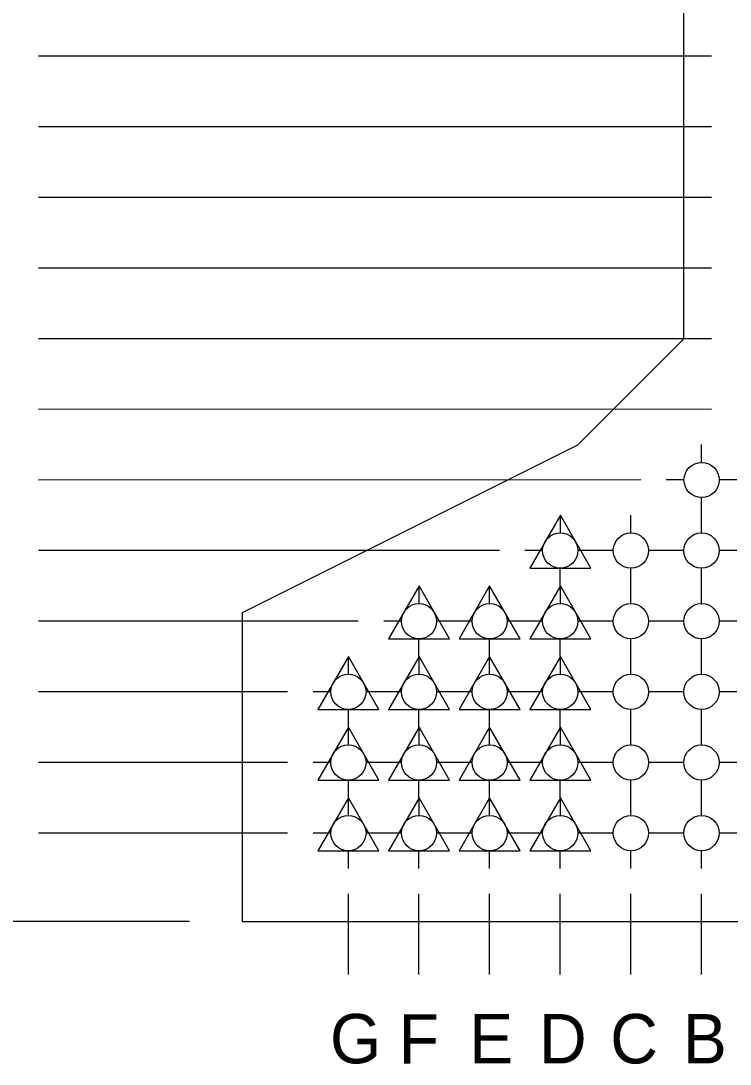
# Model space of a CAD drawing. Extents: x 998.6 to 1033.3, y 1000 to 1011.
# Drawn here: x 1009.56 to 1010.397, y 1001.342 to 1002.573 of the extents above; entities that cross this region are included whole.
import ezdxf

# ---------------------------------------------------------------- set-up
doc = ezdxf.new("R2010")
doc.units = 0
doc.layers.add('Working Level 1', color=7, linetype='Continuous')

msp = doc.modelspace()

# ---------------------------------------------------------------- linework, layer by layer
at = {"layer": 'Working Level 1'}
for p, q in [((1010.3422, 1002.1977), (1010.3422, 1004.0935)), ((1010.3747, 1002.5312), (1009.5808, 1002.5311)), ((1010.3747, 1002.4479), (1009.5808, 1002.4478)), ((1010.3747, 1002.3645), (1009.5808, 1002.3644)), ((1010.3747, 1002.2812), (1009.5808, 1002.2811)), ((1010.3747, 1002.1978), (1009.5808, 1002.1977)), ((1010.2172, 1002.0727), (1010.3422, 1002.1977)), ((1010.3747, 1002.1145), (1009.5808, 1002.1144)), ((1009.8214, 1001.8748), (1010.2172, 1002.0727)), ((1010.3631, 1002.0519), (1010.3631, 1002.0728)), ((1010.2914, 1002.0311), (1009.5808, 1002.031)), ((1010.3423, 1002.0311), (1010.3214, 1002.0311)), ((1010.4048, 1002.0311), (1010.3839, 1002.0311)), ((1010.3631, 1001.9894), (1010.3631, 1002.0103)), ((1010.1964, 1001.9894), (1010.1603, 1001.9269)), ((1010.1964, 1001.9686), (1010.1964, 1001.9894)), ((1010.2324, 1001.9269), (1010.1964, 1001.9894)), ((1010.2797, 1001.9686), (1010.2797, 1001.9894)), ((1010.3631, 1001.9686), (1010.3631, 1001.9894)), ((1010.1247, 1001.9478), (1009.5808, 1001.9477)), ((1010.1755, 1001.9478), (1010.1547, 1001.9478)), ((1010.2381, 1001.9478), (1010.2172, 1001.9478)), ((1010.2589, 1001.9478), (1010.238, 1001.9478)), ((1010.3214, 1001.9478), (1010.3005, 1001.9478)), ((1010.3422, 1001.9478), (1010.3214, 1001.9478)), ((1010.4048, 1001.9478), (1010.3839, 1001.9478)), ((1010.1603, 1001.9269), (1010.2324, 1001.9269)), ((1010.1963, 1001.9061), (1010.1963, 1001.9269)), ((1010.2797, 1001.9061), (1010.2797, 1001.9269)), ((1010.363, 1001.9061), (1010.363, 1001.9269)), ((1010.0297, 1001.9061), (1009.9936, 1001.8436)), ((1010.0297, 1001.8852), (1010.0297, 1001.9061)), ((1010.0657, 1001.8436), (1010.0297, 1001.9061)), ((1010.113, 1001.9061), (1010.0769, 1001.8436)), ((1010.113, 1001.8852), (1010.113, 1001.9061)), ((1010.1491, 1001.8436), (1010.113, 1001.9061)), ((1010.1964, 1001.9061), (1010.1603, 1001.8436)), ((1010.1964, 1001.8852), (1010.1964, 1001.9061)), ((1010.2324, 1001.8436), (1010.1964, 1001.9061)), ((1010.2797, 1001.8852), (1010.2797, 1001.9061)), ((1010.3631, 1001.8852), (1010.3631, 1001.9061)), ((1009.8214, 1001.5102), (1009.8214, 1001.8748)), ((1009.958, 1001.8644), (1009.5808, 1001.8643)), ((1010.0088, 1001.8644), (1009.988, 1001.8644)), ((1010.0714, 1001.8644), (1010.0505, 1001.8644)), ((1010.0922, 1001.8644), (1010.0713, 1001.8644)), ((1010.1547, 1001.8644), (1010.1338, 1001.8644)), ((1010.1755, 1001.8644), (1010.1547, 1001.8644)), ((1010.2381, 1001.8644), (1010.2172, 1001.8644)), ((1010.2589, 1001.8644), (1010.238, 1001.8644)), ((1010.3214, 1001.8644), (1010.3005, 1001.8644)), ((1010.3422, 1001.8644), (1010.3214, 1001.8644)), ((1010.4048, 1001.8644), (1010.3839, 1001.8644)), ((1009.9936, 1001.8436), (1010.0657, 1001.8436)), ((1010.0296, 1001.8227), (1010.0296, 1001.8436)), ((1010.0769, 1001.8436), (1010.1491, 1001.8436)), ((1010.113, 1001.8227), (1010.113, 1001.8436)), ((1010.1603, 1001.8436), (1010.2324, 1001.8436)), ((1010.1963, 1001.8227), (1010.1963, 1001.8436)), ((1010.2797, 1001.8227), (1010.2797, 1001.8436)), ((1010.363, 1001.8227), (1010.363, 1001.8436)), ((1009.9463, 1001.8227), (1009.9102, 1001.7602)), ((1009.9463, 1001.8019), (1009.9463, 1001.8227)), ((1009.9824, 1001.7602), (1009.9463, 1001.8227)), ((1010.0297, 1001.8227), (1009.9936, 1001.7602)), ((1010.0297, 1001.8019), (1010.0297, 1001.8227)), ((1010.0657, 1001.7602), (1010.0297, 1001.8227)), ((1010.113, 1001.8227), (1010.0769, 1001.7602)), ((1010.113, 1001.8019), (1010.113, 1001.8227)), ((1010.1491, 1001.7602), (1010.113, 1001.8227)), ((1010.1964, 1001.8227), (1010.1603, 1001.7602)), ((1010.1964, 1001.8019), (1010.1964, 1001.8227)), ((1010.2324, 1001.7602), (1010.1964, 1001.8227)), ((1010.2797, 1001.8019), (1010.2797, 1001.8227)), ((1010.3631, 1001.8019), (1010.3631, 1001.8227)), ((1009.8746, 1001.7811), (1009.5808, 1001.781)), ((1009.9255, 1001.7811), (1009.9046, 1001.7811)), ((1009.988, 1001.7811), (1009.9671, 1001.7811)), ((1010.0088, 1001.7811), (1009.988, 1001.7811)), ((1010.0714, 1001.7811), (1010.0505, 1001.7811)), ((1010.0922, 1001.7811), (1010.0713, 1001.7811)), ((1010.1547, 1001.7811), (1010.1338, 1001.7811)), ((1010.1755, 1001.7811), (1010.1547, 1001.7811)), ((1010.2381, 1001.7811), (1010.2172, 1001.7811)), ((1010.2589, 1001.7811), (1010.238, 1001.7811)), ((1010.3214, 1001.7811), (1010.3005, 1001.7811)), ((1010.3422, 1001.7811), (1010.3214, 1001.7811)), ((1010.4048, 1001.7811), (1010.3839, 1001.7811)), ((1009.9102, 1001.7602), (1009.9824, 1001.7602)), ((1009.9463, 1001.7394), (1009.9463, 1001.7602)), ((1009.9936, 1001.7602), (1010.0657, 1001.7602)), ((1010.0296, 1001.7394), (1010.0296, 1001.7602)), ((1010.0769, 1001.7602), (1010.1491, 1001.7602)), ((1010.113, 1001.7394), (1010.113, 1001.7602)), ((1010.1603, 1001.7602), (1010.2324, 1001.7602)), ((1010.1963, 1001.7394), (1010.1963, 1001.7602)), ((1010.2797, 1001.7394), (1010.2797, 1001.7602)), ((1010.363, 1001.7394), (1010.363, 1001.7602)), ((1009.9463, 1001.7394), (1009.9102, 1001.6769)), ((1009.9463, 1001.7185), (1009.9463, 1001.7394)), ((1009.9824, 1001.6769), (1009.9463, 1001.7394)), ((1010.0297, 1001.7394), (1009.9936, 1001.6769)), ((1010.0297, 1001.7185), (1010.0297, 1001.7394)), ((1010.0657, 1001.6769), (1010.0297, 1001.7394)), ((1010.113, 1001.7394), (1010.0769, 1001.6769)), ((1010.113, 1001.7185), (1010.113, 1001.7394)), ((1010.1491, 1001.6769), (1010.113, 1001.7394)), ((1010.1964, 1001.7394), (1010.1603, 1001.6769)), ((1010.1964, 1001.7185), (1010.1964, 1001.7394)), ((1010.2324, 1001.6769), (1010.1964, 1001.7394)), ((1010.2797, 1001.7185), (1010.2797, 1001.7394)), ((1010.3631, 1001.7185), (1010.3631, 1001.7394)), ((1009.8746, 1001.6977), (1009.5808, 1001.6976)), ((1009.9255, 1001.6977), (1009.9046, 1001.6977)), ((1009.988, 1001.6977), (1009.9671, 1001.6977)), ((1010.0088, 1001.6977), (1009.988, 1001.6977)), ((1010.0714, 1001.6977), (1010.0505, 1001.6977)), ((1010.0922, 1001.6977), (1010.0713, 1001.6977)), ((1010.1547, 1001.6977), (1010.1338, 1001.6977)), ((1010.1755, 1001.6977), (1010.1547, 1001.6977)), ((1010.2381, 1001.6977), (1010.2172, 1001.6977)), ((1010.2589, 1001.6977), (1010.238, 1001.6977)), ((1010.3214, 1001.6977), (1010.3005, 1001.6977)), ((1010.3422, 1001.6977), (1010.3214, 1001.6977)), ((1010.4048, 1001.6977), (1010.3839, 1001.6977)), ((1009.9102, 1001.6769), (1009.9824, 1001.6769)), ((1009.9463, 1001.656), (1009.9463, 1001.6769)), ((1009.9936, 1001.6769), (1010.0657, 1001.6769)), ((1010.0296, 1001.656), (1010.0296, 1001.6769)), ((1010.0769, 1001.6769), (1010.1491, 1001.6769)), ((1010.113, 1001.656), (1010.113, 1001.6769)), ((1010.1603, 1001.6769), (1010.2324, 1001.6769)), ((1010.1963, 1001.656), (1010.1963, 1001.6769)), ((1010.2797, 1001.656), (1010.2797, 1001.6769)), ((1010.363, 1001.656), (1010.363, 1001.6769)), ((1009.9463, 1001.656), (1009.9102, 1001.5935)), ((1009.9463, 1001.6352), (1009.9463, 1001.656)), ((1009.9824, 1001.5935), (1009.9463, 1001.656)), ((1010.0297, 1001.656), (1009.9936, 1001.5935)), ((1010.0297, 1001.6352), (1010.0297, 1001.656)), ((1010.0657, 1001.5935), (1010.0297, 1001.656)), ((1010.113, 1001.656), (1010.0769, 1001.5935)), ((1010.113, 1001.6352), (1010.113, 1001.656)), ((1010.1491, 1001.5935), (1010.113, 1001.656)), ((1010.1964, 1001.656), (1010.1603, 1001.5935)), ((1010.1964, 1001.6352), (1010.1964, 1001.656)), ((1010.2324, 1001.5935), (1010.1964, 1001.656)), ((1010.2797, 1001.6352), (1010.2797, 1001.656)), ((1010.3631, 1001.6352), (1010.3631, 1001.656)), ((1009.8746, 1001.6144), (1009.5808, 1001.6143)), ((1009.9255, 1001.6144), (1009.9046, 1001.6144)), ((1009.988, 1001.6144), (1009.9671, 1001.6144)), ((1010.0088, 1001.6144), (1009.988, 1001.6144)), ((1010.0714, 1001.6144), (1010.0505, 1001.6144)), ((1010.0922, 1001.6144), (1010.0713, 1001.6144)), ((1010.1547, 1001.6144), (1010.1338, 1001.6144)), ((1010.1755, 1001.6144), (1010.1547, 1001.6144)), ((1010.2381, 1001.6144), (1010.2172, 1001.6144)), ((1010.2589, 1001.6144), (1010.238, 1001.6144)), ((1010.3214, 1001.6144), (1010.3005, 1001.6144)), ((1010.3422, 1001.6144), (1010.3214, 1001.6144)), ((1010.4048, 1001.6144), (1010.3839, 1001.6144)), ((1009.9102, 1001.5935), (1009.9824, 1001.5935)), ((1009.9463, 1001.5727), (1009.9463, 1001.5935)), ((1009.9936, 1001.5935), (1010.0657, 1001.5935)), ((1010.0296, 1001.5727), (1010.0296, 1001.5935)), ((1010.0769, 1001.5935), (1010.1491, 1001.5935)), ((1010.113, 1001.5727), (1010.113, 1001.5935)), ((1010.1603, 1001.5935), (1010.2324, 1001.5935)), ((1010.1963, 1001.5727), (1010.1963, 1001.5935)), ((1010.2797, 1001.5727), (1010.2797, 1001.5935)), ((1010.363, 1001.5727), (1010.363, 1001.5935)), ((1009.9463, 1001.4477), (1009.9463, 1001.5427)), ((1010.0296, 1001.4477), (1010.0296, 1001.5427)), ((1010.113, 1001.4477), (1010.113, 1001.5427)), ((1010.1963, 1001.4477), (1010.1963, 1001.5427)), ((1010.2797, 1001.4477), (1010.2797, 1001.5427)), ((1010.363, 1001.4477), (1010.363, 1001.5427)), ((1009.7589, 1001.5102), (1009.2055, 1001.5101)), ((1009.8214, 1001.5102), (1011.1547, 1001.5102))]:
    msp.add_line(p, q, dxfattribs=at)
for centre in [(1010.3631, 1002.0311), (1010.1963, 1001.9478), (1010.2797, 1001.9478), (1010.363, 1001.9478), (1010.0296, 1001.8644), (1010.113, 1001.8644), (1010.1963, 1001.8644), (1010.2797, 1001.8644), (1010.363, 1001.8644), (1009.9463, 1001.7811), (1010.0296, 1001.7811), (1010.113, 1001.7811), (1010.1963, 1001.7811), (1010.2797, 1001.7811), (1010.363, 1001.7811), (1009.9463, 1001.6977), (1010.0296, 1001.6977), (1010.113, 1001.6977), (1010.1963, 1001.6977), (1010.2797, 1001.6977), (1010.363, 1001.6977), (1009.9463, 1001.6144), (1010.0296, 1001.6144), (1010.113, 1001.6144), (1010.1963, 1001.6144), (1010.2797, 1001.6144), (1010.363, 1001.6144)]:
    msp.add_circle(centre, 0.0208, dxfattribs=at)

# ---------------------------------------------------------------- texts
for s, p in [('G', (1009.9246, 1001.3427)), ('F', (1010.0057, 1001.3423)), ('E', (1010.0889, 1001.3426)), ('D', (1010.1712, 1001.3426)), ('C', (1010.2552, 1001.3426)), ('B', (1010.3409, 1001.3426))]:
    msp.add_text(s, height=0.0583, dxfattribs=at).set_placement(p)

doc.saveas('drawing.dxf')
